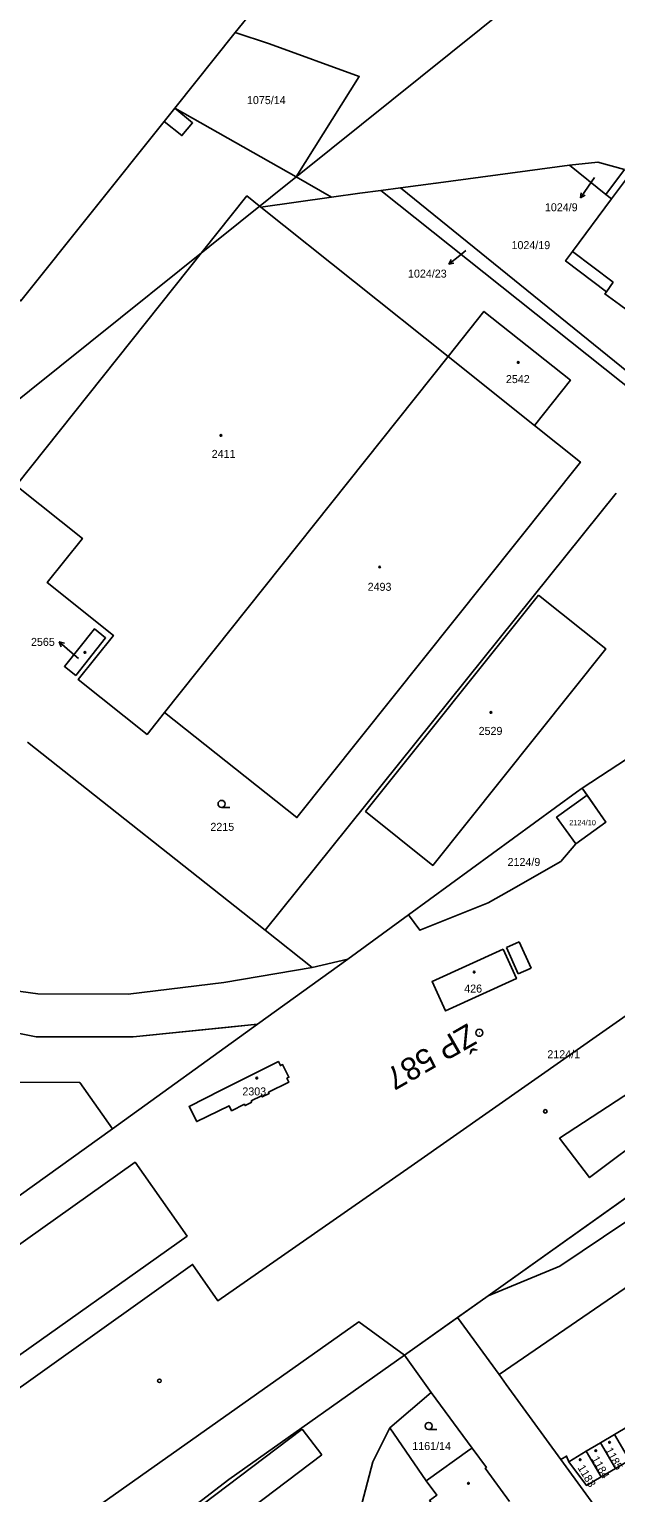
# Model space of a CAD drawing. Extents: x -793666 to -785424, y -1118958 to -1108761.
# Drawn here: x -792344.1 to -792219.4, y -1109916.5 to -1109605.6 of the extents above; entities that cross this region are included whole.
import ezdxf

# ---------------------------------------------------------------- set-up
doc = ezdxf.new("R2010")
doc.units = 0
for name, color, linetype in [('1', 7, 'Continuous'), ('1_2000 - úřady', 7, 'Continuous'), ('Hranice parcel', 7, 'Continuous'), ('Parcelní čísla', 7, 'Continuous'), ('Pop  PČ popisy', 7, 'Continuous'), ('Vnitřní kresba', 7, 'Continuous'), ('Vrstva 53', 7, 'Continuous'), ('Vrstva 63', 7, 'Continuous'), ('Značky budov', 7, 'Continuous'), ('Značky kultur', 7, 'Continuous')]:
    doc.layers.add(name, color=color, linetype=linetype)

msp = doc.modelspace()

# ---------------------------------------------------------------- linework, layer by layer
at = {"layer": '1'}
msp.add_line((-792196.9, -1109800.79), (-792262.89, -1109847.12), dxfattribs=at)
msp.add_lwpolyline([(-792262.89, -1109847.12), (-792303.98, -1109875.73), (-792309.37, -1109867.98), (-792381.88, -1109919.59), (-792373.33, -1109931.54)], dxfattribs=at)
for centre in [(-792234.4, -1109835.46), (-792316.42, -1109892.69)]:
    msp.add_circle(centre, 0.375, dxfattribs=at)
at = {"layer": '1_2000 - úřady'}
msp.add_lwpolyline([(-791938.08, -1109742.36), (-792598.01, -1110271.46), (-792786.15, -1110036.8), (-792126.22, -1109507.7)], close=True, dxfattribs=at)
at = {"layer": 'Hranice parcel'}
for p, q in [((-792313.11, -1109622.33), (-792300.29, -1109606.28)), ((-792287.32, -1109636.9), (-792313.11, -1109622.33)), ((-792229.23, -1109634.41), (-792257.13, -1109638.17)), ((-792229.23, -1109634.41), (-792221.51, -1109640.65)), ((-792213.73, -1109632.8), (-792220.3, -1109641.62)), ((-792279.86, -1109641.23), (-792287.32, -1109636.9)), ((-792221.51, -1109640.65), (-792217.57, -1109635.36)), ((-792294.9, -1109643.34), (-792279.86, -1109641.23)), ((-792265.17, -1109639.25), (-792269.36, -1109639.81)), ((-792220.3, -1109641.62), (-792221.51, -1109640.65)), ((-792255.07, -1109675.08), (-792294.9, -1109643.34)), ((-792315.33, -1109750.72), (-792255.07, -1109675.08)), ((-792236.7, -1109689.73), (-792255.07, -1109675.08)), ((-792219.35, -1109704.16), (-792293.96, -1109796.98)), ((-792293.96, -1109796.98), (-792344.46, -1109757.04)), ((-792226.53, -1109766.83), (-792225.52, -1109768.27)), ((-792276.34, -1109803.1), (-792263.48, -1109793.72)), ((-792283.96, -1109804.89), (-792293.96, -1109796.98)), ((-792295.56, -1109816.94), (-792276.34, -1109803.1)), ((-792283.96, -1109804.89), (-792276.34, -1109803.1)), ((-792326.43, -1109839.17), (-792295.56, -1109816.94)), ((-792246.55, -1109874.61), (-792164.73, -1109816.44)), ((-792147.85, -1109825.45), (-792244.24, -1109891.34)), ((-792253.05, -1109879.23), (-792246.55, -1109874.61)), ((-792253.05, -1109879.23), (-792264.32, -1109887.25)), ((-792244.24, -1109891.34), (-792253.05, -1109879.23)), ((-792258.68, -1109895.18), (-792264.32, -1109887.25)), ((-792267.43, -1109902.7), (-792258.68, -1109895.18)), ((-792249.95, -1109906.97), (-792258.68, -1109895.18)), ((-792216.72, -1109902.36), (-792219.71, -1109904.13)), ((-792267.43, -1109902.7), (-792259.72, -1109913.93)), ((-792219.71, -1109904.13), (-792222.7, -1109905.9)), ((-792216.52, -1109909.52), (-792219.71, -1109904.13)), ((-792225.68, -1109907.66), (-792229.39, -1109909.91)), ((-792222.7, -1109905.9), (-792225.68, -1109907.66)), ((-792222.49, -1109913.06), (-792225.68, -1109907.66)), ((-792219.5, -1109911.29), (-792222.7, -1109905.9)), ((-792222.49, -1109913.06), (-792219.5, -1109911.29)), ((-792219.5, -1109911.29), (-792216.52, -1109909.52))]:
    msp.add_line(p, q, dxfattribs=at)
for points in [[(-792300.29, -1109606.28), (-792296.3, -1109601.29), (-792296.46, -1109601.17), (-792295.65, -1109600.16)], [(-792287.32, -1109636.9), (-792273.94, -1109615.61), (-792293.05, -1109608.68), (-792300.29, -1109606.28)], [(-792355.96, -1109661.07), (-792353.1, -1109657.6), (-792345.85, -1109663.28), (-792315.38, -1109625.16), (-792311.64, -1109628.15), (-792309.39, -1109625.46), (-792313.11, -1109622.33)], [(-792217.57, -1109635.36), (-792223.23, -1109633.79), (-792229.23, -1109634.41)], [(-792257.13, -1109638.17), (-792257.66, -1109638.27), (-792265.17, -1109639.25)], [(-792346.37, -1109702.94), (-792346.88, -1109702.53), (-792297.84, -1109640.99), (-792294.9, -1109643.34)], [(-792269.36, -1109639.81), (-792273.82, -1109640.41), (-792279.86, -1109641.23)], [(-792269.36, -1109639.81), (-792207.16, -1109689.36), (-792204.47, -1109691.5), (-792204.05, -1109691.84)], [(-792265.17, -1109639.25), (-792207.01, -1109686.37), (-792203.19, -1109687.6), (-792199.7, -1109685.86), (-792186.33, -1109669.08)], [(-792191.31, -1109665.06), (-792200.45, -1109677.48), (-792203.54, -1109675.23), (-792211.54, -1109669.29), (-792218.63, -1109664.04), (-792221.71, -1109661.79), (-792221.38, -1109661.32), (-792230.1, -1109654.77), (-792228.64, -1109652.81), (-792220.3, -1109641.62)], [(-792255.07, -1109675.08), (-792247.45, -1109665.51), (-792229.07, -1109680.15), (-792236.7, -1109689.73)], [(-792236.7, -1109689.73), (-792226.93, -1109697.52), (-792287.19, -1109773.06), (-792315.33, -1109750.72)], [(-792346.37, -1109702.94), (-792332.79, -1109713.75), (-792340.26, -1109723.13), (-792326.19, -1109734.34), (-792333.66, -1109743.71), (-792319.04, -1109755.37), (-792315.33, -1109750.72)], [(-792235.81, -1109725.77), (-792221.5, -1109737.22), (-792258.33, -1109783.22), (-792272.59, -1109771.72), (-792235.81, -1109725.77)], [(-792334.22, -1109742.85), (-792336.62, -1109740.94), (-792330.24, -1109732.98), (-792327.86, -1109734.89), (-792334.22, -1109742.85)], [(-792226.53, -1109766.83), (-792215.1, -1109759.26), (-792190.07, -1109741.13), (-792187.8, -1109739.49), (-792182.21, -1109735.57)], [(-792263.48, -1109793.72), (-792227.74, -1109767.63), (-792226.53, -1109766.83)], [(-792227.91, -1109778.64), (-792232.01, -1109772.96), (-792225.52, -1109768.27)], [(-792225.52, -1109768.27), (-792221.5, -1109774), (-792227.91, -1109778.64)], [(-792227.91, -1109778.64), (-792231.12, -1109782.39), (-792242.15, -1109788.7), (-792246.57, -1109791.13), (-792261.09, -1109796.98), (-792263.48, -1109793.72)], [(-792243.33, -1109801.02), (-792258.45, -1109807.89), (-792255.62, -1109814.12), (-792240.53, -1109807.23), (-792243.33, -1109801.02)], [(-792379.5, -1109803.55), (-792361.45, -1109807.85), (-792342.29, -1109810.51), (-792323.04, -1109810.54), (-792302.75, -1109808.06), (-792283.96, -1109804.89)], [(-792295.56, -1109816.94), (-792301.6, -1109817.55), (-792322.02, -1109819.61), (-792342.61, -1109819.6), (-792359.93, -1109816.17), (-792381.95, -1109813.67)], [(-792149.91, -1109821.24), (-792150.43, -1109821.57), (-792155.08, -1109814.18), (-792175.53, -1109829.37), (-792217.28, -1109858.93), (-792231.29, -1109868.36), (-792246.55, -1109874.61)], [(-792197.4, -1109828.81), (-792224.99, -1109849.52), (-792231.36, -1109841.16), (-792202.2, -1109822.1)], [(-792296.75, -1109833.5), (-792296.89, -1109833.23), (-792294.69, -1109832.12), (-792294.55, -1109832.4), (-792293.11, -1109831.67), (-792293.24, -1109831.4), (-792288.91, -1109829.23), (-792289.32, -1109828.42), (-792288.88, -1109828.19), (-792290.24, -1109825.5), (-792290.69, -1109825.73), (-792291.12, -1109824.89), (-792303.27, -1109830.97), (-792310.11, -1109834.39), (-792308.49, -1109837.63), (-792301.63, -1109834.25), (-792301.09, -1109835.33), (-792298.34, -1109833.96), (-792298.21, -1109834.23), (-792296.75, -1109833.5)], [(-792326.43, -1109839.17), (-792333.34, -1109829.35), (-792386.68, -1109829.15)], [(-792424.2, -1109907.16), (-792385.97, -1109878.06), (-792389.09, -1109874.23), (-792363.55, -1109861.57), (-792349.96, -1109854.83), (-792346.23, -1109853.43), (-792326.43, -1109839.17)], [(-792350.32, -1109890.12), (-792310.53, -1109861.95), (-792321.58, -1109846.27), (-792361.41, -1109874.49), (-792361.79, -1109874.77), (-792365.28, -1109869.81), (-792377.79, -1109878.69), (-792372.64, -1109886.06), (-792380.76, -1109891.84), (-792386.94, -1109896.32), (-792378.6, -1109908.09), (-792372.63, -1109903.82), (-792364.77, -1109898.2), (-792363.05, -1109900.6), (-792354.69, -1109894.62), (-792355.34, -1109893.72), (-792350.32, -1109890.12)], [(-792367.46, -1109942.54), (-792356.82, -1109934.38), (-792354.59, -1109937.05), (-792274.06, -1109880.18), (-792264.32, -1109887.25)], [(-792264.32, -1109887.25), (-792299.96, -1109912.47), (-792301.66, -1109913.67), (-792313.28, -1109922.6)], [(-792244.24, -1109891.34), (-792242.7, -1109893.46), (-792231.08, -1109909.43)], [(-792266.09, -1109941.85), (-792278.7, -1109939.11), (-792271.06, -1109909.92), (-792267.43, -1109902.7)], [(-792249.95, -1109906.97), (-792250.42, -1109907.31), (-792259.72, -1109913.93)], [(-792242, -1109918.31), (-792247.15, -1109911.27), (-792246.92, -1109911.11), (-792249.95, -1109906.97)], [(-792231.08, -1109909.43), (-792229.89, -1109908.7), (-792229.39, -1109909.91)], [(-792231.08, -1109909.43), (-792219.92, -1109924.78), (-792218.94, -1109924.87)], [(-792229.39, -1109909.91), (-792225.67, -1109914.91), (-792222.49, -1109913.06)], [(-792259.72, -1109913.93), (-792257.44, -1109916.97), (-792259, -1109918.14), (-792254.29, -1109924.44), (-792252.74, -1109923.24), (-792251.4, -1109925.12)]]:
    msp.add_lwpolyline(points, dxfattribs=at)
at = {"layer": 'Pop  PČ popisy'}
for p, q in [((-792223.95, -1109637.03), (-792225.21, -1109638.91)), ((-792225.21, -1109638.91), (-792226.89, -1109641.4)), ((-792226.89, -1109641.4), (-792226.74, -1109640.29)), ((-792226.89, -1109641.4), (-792225.91, -1109640.85)), ((-792252.57, -1109653.61), (-792254.9, -1109655.5)), ((-792251.32, -1109652.59), (-792252.57, -1109653.61)), ((-792254.9, -1109655.5), (-792254.44, -1109654.48)), ((-792254.9, -1109655.5), (-792253.81, -1109655.26)), ((-792335.44, -1109737.68), (-792337.71, -1109735.71)), ((-792337.71, -1109735.71), (-792336.62, -1109735.99)), ((-792337.71, -1109735.71), (-792337.28, -1109736.75)), ((-792333.65, -1109739.22), (-792335.44, -1109737.68))]:
    msp.add_line(p, q, dxfattribs=at)
at = {"layer": 'Vnitřní kresba'}
for p, q in [((-792313.11, -1109622.33), (-792315.38, -1109625.16)), ((-792228.64, -1109652.81), (-792219.94, -1109659.27)), ((-792219.94, -1109659.27), (-792221.38, -1109661.32)), ((-792242.67, -1109800.66), (-792239.95, -1109799.43)), ((-792239.95, -1109799.43), (-792237.42, -1109805.03)), ((-792240.14, -1109806.26), (-792242.67, -1109800.66)), ((-792237.42, -1109805.03), (-792240.14, -1109806.26)), ((-792312.57, -1109922.99), (-792286.05, -1109902.96)), ((-792286.05, -1109902.96), (-792281.92, -1109908.45)), ((-792281.92, -1109908.45), (-792308.48, -1109928.46))]:
    msp.add_line(p, q, dxfattribs=at)
at = {"layer": 'Vrstva 53'}
for points in [[(-792359.93, -1109816.17), (-792342.61, -1109819.6), (-792322.02, -1109819.61), (-792295.56, -1109816.94), (-792276.34, -1109803.1), (-792263.48, -1109793.72), (-792261.09, -1109796.98), (-792246.57, -1109791.13), (-792242.15, -1109788.7), (-792231.12, -1109782.39), (-792227.91, -1109778.64), (-792221.5, -1109774), (-792226.53, -1109766.83), (-792215.1, -1109759.26)], [(-792164.73, -1109816.44), (-792246.55, -1109874.61), (-792264.32, -1109887.25), (-792274.06, -1109880.18)], [(-792346.23, -1109853.43), (-792326.43, -1109839.17), (-792333.34, -1109829.35), (-792386.68, -1109829.15)], [(-792274.06, -1109880.18), (-792354.59, -1109937.05), (-792356.82, -1109934.38), (-792367.46, -1109942.54), (-792370.89, -1109945.17), (-792383.68, -1109958.07), (-792389.98, -1109953.44), (-792394.9, -1109948.21), (-792395.36, -1109947.72), (-792395.96, -1109947.08), (-792396.36, -1109947.46), (-792401.63, -1109940.01), (-792401.09, -1109939.74), (-792401.42, -1109939.07), (-792404.43, -1109932.95), (-792404.35, -1109930.54), (-792406.09, -1109932.53), (-792409.46, -1109929.26), (-792407.99, -1109927.32), (-792424.2, -1109907.16), (-792385.97, -1109878.06), (-792389.09, -1109874.23), (-792363.55, -1109861.57)]]:
    msp.add_lwpolyline(points, dxfattribs=at)
at = {"layer": 'Vrstva 63'}
msp.add_line((-792248.48, -1109818.75), (-792248.38, -1109818.75), dxfattribs=at)
msp.add_circle((-792248.43, -1109818.75), 0.756, dxfattribs=at)
at = {"layer": 'Značky budov'}
for centre in [(-792240.16, -1109676.36), (-792303.36, -1109691.86), (-792269.61, -1109719.81), (-792332.26, -1109737.96), (-792245.97, -1109750.71), (-792249.52, -1109805.87), (-792295.73, -1109828.39), (-792220.75, -1109905.75), (-792223.67, -1109907.53), (-792226.99, -1109909.46), (-792250.74, -1109914.47)]:
    msp.add_circle(centre, 0.175, dxfattribs=at)
at = {"layer": 'Značky kultur'}
for p, q in [((-792303.21, -1109770.88), (-792301.46, -1109770.88)), ((-792259.19, -1109903.04), (-792257.44, -1109903.04))]:
    msp.add_line(p, q, dxfattribs=at)
for centre in [(-792303.21, -1109770.13), (-792259.19, -1109902.29)]:
    msp.add_circle(centre, 0.75, dxfattribs=at)

# ---------------------------------------------------------------- texts
at = {"layer": 'Parcelní čísla'}
for s, height, p in [('1075/14', 1.7, (-792297.81, -1109621.47)), ('1024/9', 1.7, (-792234.48, -1109644.24)), ('1024/19', 1.7, (-792241.58, -1109652.28)), ('1024/23', 1.7, (-792263.58, -1109658.33)), ('2542', 1.7, (-792242.77, -1109680.74)), ('2411', 1.7, (-792305.31, -1109696.63)), ('2493', 1.7, (-792272.16, -1109724.87)), ('2565', 1.7, (-792343.72, -1109736.57)), ('2529', 1.7, (-792248.57, -1109755.48)), ('2215', 1.7, (-792305.59, -1109775.86)), ('2124/10', 1.139, (-792229.33, -1109774.68)), ('2124/9', 1.7, (-792242.42, -1109783.33)), ('426', 1.7, (-792251.63, -1109810.22)), ('2124/1', 1.7, (-792233.96, -1109824.17)), ('2303', 1.7, (-792298.79, -1109832.07)), ('1161/14', 1.7, (-792262.67, -1109907.4))]:
    msp.add_text(s, height=height, dxfattribs=at).set_placement(p)
for s, rotation, p in [('1184', 299, (-792224.61, -1109909.25)), ('1185', 298, (-792221.71, -1109907.37)), ('1183', 301, (-792227.6, -1109911.16))]:
    msp.add_text(s, height=1.7, rotation=rotation, dxfattribs=at).set_placement(p)
at = {"layer": 'Vrstva 63'}
msp.add_text('ŽP 587', height=4.8, rotation=209.8738, dxfattribs=at).set_placement((-792250.88, -1109816.64))

doc.saveas('drawing.dxf')
